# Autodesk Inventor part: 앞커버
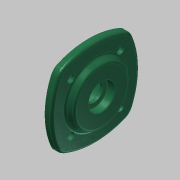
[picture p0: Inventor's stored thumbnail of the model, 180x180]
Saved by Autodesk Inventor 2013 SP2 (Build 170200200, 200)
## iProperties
Created: 2015-11
Part Number: 앞커버
Material: 일반
Document SubType Name: Modeling
Designer: mduedu
Density: 1 g/cm^3
Author: mduedu
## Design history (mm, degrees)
sketch "스케치1"
  geometry: L1 (50, 50)-(-50, 50); L2 (-50, 50)-(-50, -50); L3 (-50, -50)-(50, -50); L4 (50, -50)-(50, 50); L5 (0, 50)-(0, -50); L6 (50, 0)-(-50, 0); A1 r 90 centre (-40, 0) between (40.415, -40.415) and (40.415, 40.415); A2 r 90 centre (40, 0) between (-40.415, 40.415) and (-40.415, -40.415); A3 r 90 centre (0, -40) between (40.415, 40.415) and (-40.415, 40.415); A4 r 90 centre (0, 40) between (-40.415, -40.415) and (40.415, -40.415); 2 further points
  constraints: 12 end point, 8 point on circle, 5 midpoint, 4 centre point, 2 horizontal alignment, 2 parallel, 2 perpendicular, 2 symmetric about line, 2 tangent, 2 vertical alignment, 1 equal radius, 1 horizontal, 2 other
  dimensions: "d0" = 100 distance of L3.end L1.start; "d2" = 90 radius of A1
extrude "돌출1" new body sketch "스케치1" distance "d3" = 8; taper "d4" = 0 deg
sketch "스케치2"
  geometry: C1 r 35 at (0, 0); 1 further point
  constraints: 1 centre point, 1 coincident
  dimensions: "d5" = 70 diameter of C1
extrude "돌출2" join sketch "스케치2" distance "d6" = 7; taper "d7" = -30 deg
sketch "스케치3"
  geometry: L1 (0, 0)-(0, 40); L2 (0, 0)-(-28.284, 28.284); A1 r 40 centre (0, 0) between (0, 40) and (-28.284, 28.284); 2 further points
  constraints: 4 end point, 2 coincident, 2 point on circle, 1 centre point, 1 vertical
  dimensions: "d8" = 80 diameter of A1; "d9" = 45 deg angle of L1 L2
hole "구멍1" sketch "스케치3" at (-28.284, 28.284) diameter "d11" = 4.5; stored, may be unused: countersink angle "d15" = 90 deg, drill point angle "d17" = 118 deg; dims "d12" = 6, "d13" = 8, "d14" = 4.4, "d16" = 8
sketch "스케치4"
  geometry: C1 r 35 at (0, 0); 1 further point
  constraints: 1 centre point, 1 coincident
  dimensions: "d21" = 70 diameter of C1
extrude "돌출3" join sketch "스케치4" distance "d23" = 12; taper "d24" = 0 deg
hole "구멍2" diameter "d27" = 30; stored, may be unused: countersink angle "d31" = 90 deg, drill point angle "d33" = 0 deg; dims "d25" = 10, "d26" = 10, "d28" = 6, "d29" = 40, "d30" = 12, "d32" = 15
fillet "모깎기2" dims "d35" = 15
fillet "모깎기3" dims "d36" = 3
fillet "모깎기4" dims "d37" = 3
fillet "모깎기5" dims "d38" = 0.3
chamfer "모따기1" distance "d39" = 1; stored, may be unused: second distance "d40" = 2, angle "d41" = 45 deg
hole "구멍3" diameter "d44" = 20; stored, may be unused: countersink angle "d48" = 90 deg, drill point angle "d50" = 118 deg; dims "d45" = 6, "d46" = 30, "d47" = 8.7, "d49" = 8, "d55" = 10, "d56" = 10
fillet "모깎기6" dims "d51" = 0.3
chamfer "모따기2" distance "d52" = 0.7; stored, may be unused: second distance "d53" = 2, angle "d54" = 30 deg
node "솔리드1"
pattern_circular "원형 패턴1" dims angle "d19" = 360 deg
